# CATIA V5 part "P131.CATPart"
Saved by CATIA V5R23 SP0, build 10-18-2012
Part number: P131
Definition: Vis Chc M6x25
Description: ISO 4762 Vis Chc M6x25
Publications: "Mating Edge", "Axis"
Bounding box of the stored display mesh (mm): x -25 to 6, y -5 to 5, z -5 to 5
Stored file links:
  C:\wamp\www\COURS\CONCEPTION GMP1\TITRE 02-SEMESTRE 2\03-TP7-PRESSE MECANIQUE\eleve\P131.CATPart
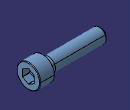
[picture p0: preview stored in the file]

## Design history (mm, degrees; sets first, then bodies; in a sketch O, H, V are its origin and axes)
Parameters
  Material = "St"
  d_dia = 6 mm
  l_nom = 25 mm
  k_head_depth_max = 6 mm
  s_nom = 5 mm
  r_min = 0.25 mm
  ds_max = 6 mm
  e = 5.72 mm
  t_min = 3 mm
  p_pitch = 1 mm
  Threading = 22.5 mm
  dk_max = 10 mm
  PartNumber = "ISO 4762 Vis Chc M6x25"
Body1 "PartBody" (main body)
  Sketch1 on yz-plane, origin (0, 0, 0), H (0, 1, 0), V (0, 0, 1)
    circle A1 centre (0, 0) radius 5
    radius A1 = 5 {= dk_max /2}
  Pad1: profile Sketch1, direction (1, 0, 0), length 6 {= k_head_depth_max}
  Fillet1: radius 0.25 {= r_min}, on edge [face of Pad1 | face of Pad1]
  Body2
    Sketch2 on face of Pad1, origin (6, 0, 0), H (0, 1, 0), V (0, 0, 1)
      point P1 (2.5, -1.4434)
      point P2 (2.5, 1.4434)
      point P3 (0, 2.8868)
      point P4 (-2.5, 1.4434)
      point P5 (-2.5, -1.4434)
      point P6 (0, -2.8868)
      point P7 (2.5, 0)
      line L1 (2.5, -1.4434) -> (2.5, 1.4434)
      line L2 (2.5, 1.4434) -> (0, 2.8868)
      line L3 (0, 2.8868) -> (-2.5, 1.4434)
      line L4 (-2.5, 1.4434) -> (-2.5, -1.4434)
      line L5 (-2.5, -1.4434) -> (0, -2.8868)
      line L6 (0, -2.8868) -> (2.5, -1.4434)
      construction line L7 (0, 0) -> (2.5, 0)
      construction circle A1 centre (0, 0) radius 2.8868
      construction arc A2 centre (-2.5, -1.4434) radius 2.8868 from (-2.5, 1.4434) to (0, -2.8868) cw
      construction arc A3 centre (2.5, 1.4434) radius 2.8868 from (0, 2.8868) to (2.5, -1.4434) ccw
      point P8 (-2.5, -1.4434)
      point P9 (2.5, 1.4434)
      distance L1 L4 = 5 {= s_nom}
      horizontal: L7 H
      coincidence: A1 P1, A1 P2, A1 P3, A1 P4, A1 P5, A1 P6, A2 P4, A2 P6, A2 O, P8 P5, A3 P3, A3 P1, A3 O, P9 P2
      midpoint: P7 L1
    Pad2: profile Sketch2, direction (-1, 0, 0), length 4.6484 {= t_min +(e /3.47)}
    Body3
      Sketch3 on zx-plane, origin (0, 0, 0), H (-1, 0, 0), V (0, 0, 1)
        point P1 (-1.3488, 0)
        line L1 (-1.3488, 0) -> (-3, 2.86)
        line L2 (-3, 2.86) -> (-6, 2.86)
        line L3 (-6, 2.86) -> (-6, 0)
        axis line L4 (-46.2384, 0) -> (26.3409, 0)
        reference projected line E1 (-6, -6.9227) -> (-6, 6.9227) from edge [face of Pad2 | face of Pad2]
        length L2 = 3 {= t_min}
        angle L1 L4 = 60
        distance L2 L4 = 2.86 {= e /2}
        horizontal: L2 H, L4 H
        perpendicularity: L3 L2
        fix: L4
        coincidence: L3 E1, P1 L4
      Shaft1: profile Sketch3, axis Sketch3.L4, angle 360
    Intersect1: tool Body3
  Remove1: tool Body2
  Sketch4 on xy-plane, origin (0, 0, 0), H (1, 0, 0), V (0, 1, 0)
    line L1 (0, 0) -> (0, 3)
    line L2 (0, 3) -> (-2.5, 3)
    line L3 (-2.5, 3) -> (-2.5, 2.9268)
    line L4 (-2.5, 2.9268) -> (-25, 2.9268)
    line L5 (-25, 2.9268) -> (-25, 0)
    axis line L6 (-192.3446, 0) -> (99.1594, 0)
    distance L5 L1 = 25 {= l_nom}
    distance L3 L5 = 22.5 {= Threading}
    distance L2 L6 = 3 {= ds_max /2}
    distance L4 L6 = 2.9268 {= d_dia /2.05}
    vertical: L1 V, L3 V, L5 V
    horizontal: L2 H, L4 H, L6 H
    fix: L6
  Shaft2: profile Sketch4, axis Sketch4.L6, angle 360
  Fillet2: radius 0.25 {= r_min}, on edge [face of Shaft2 | face of Pad1]
  Chamfer1: length 1 {= p_pitch}, angle 45, on edge [face of Shaft2 | face of Shaft2]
